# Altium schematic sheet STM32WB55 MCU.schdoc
size 297 x 209 mm; Symbol: Drawing-Symbol_A4; @Project Name: Hưhwwuey; @Page Count: 3; @Update Date: 2026-10-10; @Create Date: 2026-10-10; @Schematic Name: Schematic1; @Page No: 3; @Page Name: P1; Company: EasyEDA.com; Version: V1.0; Page Size: A4; Device: Drawing-Symbol_A4; @Create Time: 11:30:46; @Update Time: 11:30:46; Border: 1; Width: 1170; Height: 825; Region Start: 1; X Region Count: 6; Y Region Count: 4; Blade Width: 10; Title Block Position: 3; @Board Name: Board1
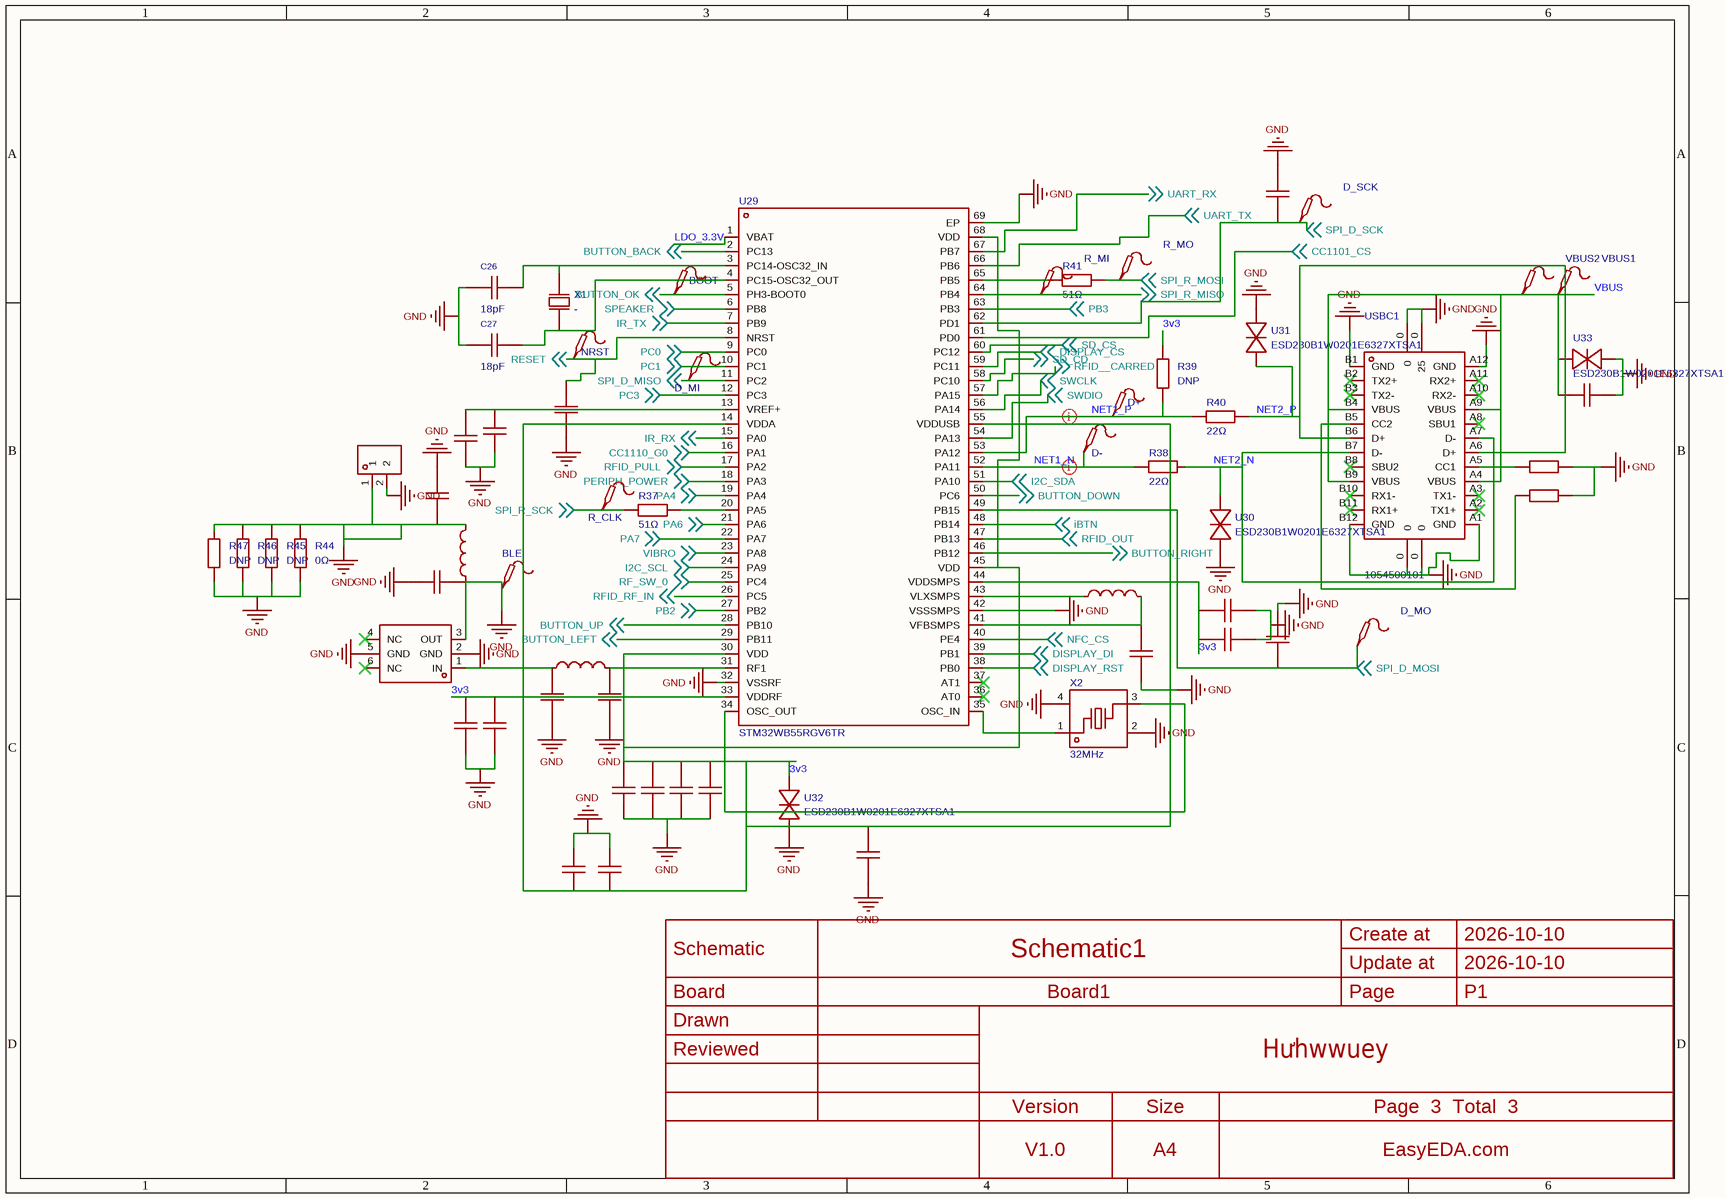
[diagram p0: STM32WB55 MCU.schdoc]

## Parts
C26  18pF  [C0402]
C27  18pF  [C0402]
C28  DNP  [C0402]  (value not drawn)
C29  DNP  [C0402]  (value not drawn)
C30  100nF  [C0402]  (value not drawn)
C31  0.8pf  [C0402]  (value not drawn)
C32  0.3PF  [C0402]  (value not drawn)
C33  100nF  [C0402]  (value not drawn)
C34  100nF  [C0402]  (value not drawn)
C35  100nF  [C0402]  (value not drawn)
C36  4.7uF  [C0402]  (value not drawn)
C37  100nF  [C0402]  (value not drawn)
C38  1nF  [C0402]  (value not drawn)
C39  10nF  [C0402]  (value not drawn)
C40  1nF  [C0402]  (value not drawn)
C41  100nF  [C0402]  (value not drawn)
C42  100nF  [C0402]  (value not drawn)
C43  100pF  [C0402]  (value not drawn)
C44  4.7uF  [C0402]  (value not drawn)
C45  4.7uF  [C0402]  (value not drawn)
C46  100nF  [C0402]  (value not drawn)
C47  100nF  [C0402]  (value not drawn)
C48  1.5pF  [C0402]  (value not drawn)
C49  100nF  [C0402]  (value not drawn)
D-  (no value)  [Test-Point-0.5mm]
FL1  LFL182G45TC1A108  [FILTET-SMD_0603-6P-L1.6-W0.8-P0.50_LFL182G45TC1A108]  (value not drawn)
L4  2.7nh  [L0805]  (value not drawn)
L5  10uH  [L0805]  (value not drawn)
L6  3nH  [L0402]  (value not drawn)
R37  51Ω  [R0402]
R38  22Ω  [R0402]
R39  DNP  [R0402]
R40  22Ω  [R0402]
R41  51Ω  [R0402]
R42  5.1K  [R1206]  (value not drawn)
R43  5.1K  [R1206]  (value not drawn)
R44  0Ω  [R0402]
R45  DNP  [R0402]
R46  DNP  [R0402]
R47  DNP  [R0402]
R_CLK  (no value)  [Test-Point-0.5mm]
TP5  D+  [Test-Point-0.5mm]
TP6  D_MI  [Test-Point-0.5mm]
TP7  R_MI  [Test-Point-0.5mm]
TP8  R_MO  [Test-Point-0.5mm]
TP9  D_MO  [Test-Point-0.5mm]
TP10  D_SCK  [Test-Point-0.5mm]
TP11  BOOT  [Test-Point-0.5mm]
TP12  NRST  [Test-Point-0.5mm]
TP13  VBUS2  [Test-Point-0.5mm]
TP14  VBUS1  [Test-Point-0.5mm]
TP15  BLE  [Test-Point-0.5mm]
U29  STM32WB55RGV6TR  [QFN-68_L8.0-W8.0-P0.40-TL-EP6.4]
U30  ESD230B1W0201E6327XTSA1  [WLL-2-1_L0.6-W0.3-BI]
U31  ESD230B1W0201E6327XTSA1  [WLL-2-1_L0.6-W0.3-BI]
U32  ESD230B1W0201E6327XTSA1  [WLL-2-1_L0.6-W0.3-BI]
U33  ESD230B1W0201E6327XTSA1  [WLL-2-1_L0.6-W0.3-BI]
U34  1001312  [ANT-SMD_L2.0-W1.2-BI]  (value not drawn)
USBC1  1054500101  [USB-C-SMD_TYPE-C-USB-18]
X1  -  [CRYSTAL-SMD_L3.2-W1.5-1]
X2  32MHz  [CRYSTAL-SMD_4P-L3.2-W2.5-BL]

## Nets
GND: C26.1 C27.1 C28.1 C29.1 C30.2 C31.2 C32.2 C33.2 C34.2 C35.2 C36.1 C37.2 C38.2 C39.2 C40.1 C41.2 C42.2 C43.1 C44.1 C45.1 C46.1 C47.1 C48.1 C48.2 C49.1 C49.2 FL1.2(GND) FL1.3(OUT) FL1.5(GND) L6.1 L6.2 R42.2 R43.2 R44.1 R44.2 R45.1 R45.2 R46.1 R46.2 R47.1 R47.2 TP15.1 U29.32(VSSRF) U29.42(VSSSMPS) U29.69(EP) U30.1(C) U31.2(A) U32.1(C) U33.1(C) U34.1 U34.2 USBC1.0 USBC1.A1(GND) USBC1.A12(GND) USBC1.B1(GND) USBC1.B12(GND) X2.2(GND) X2.4(GND)
3v3: C33.1 C34.1 C35.1 C36.2 C37.1 C38.1 C39.1 C42.1 C43.2 C45.2 C46.2 R39.2 U29.14(VDDA) U29.30(VDD) U29.33(VDDRF) U29.44(VDDSMPS) U29.45(VDD) U29.55(VDDUSB) U29.68(VDD) U32.2(A)
BUTTON_BACK: U29.2(PC13) ; off-sheet BUTTON_BACK
BUTTON_DOWN: U29.50(PC6) ; off-sheet BUTTON_DOWN
BUTTON_LEFT: U29.29(PB11) ; off-sheet BUTTON_LEFT
BUTTON_OK: TP11.1 U29.5(PH3-BOOT0) ; off-sheet BUTTON_OK
BUTTON_RIGHT: U29.46(PB12) ; off-sheet BUTTON_RIGHT
BUTTON_UP: U29.28(PB10) ; off-sheet BUTTON_UP
CC1101_CS: U29.61(PD0) ; off-sheet CC1101_CS
CC1110_G0: U29.16(PA1) ; off-sheet CC1110_G0
DISPLAY_CS: U29.59(PC11) ; off-sheet DISPLAY_CS
DISPLAY_DI: U29.39(PB1) ; off-sheet DISPLAY_DI
DISPLAY_RST: U29.38(PB0) ; off-sheet DISPLAY_RST
I2C_SCL: U29.24(PA9) ; off-sheet I2C_SCL
I2C_SDA: U29.51(PA10) ; off-sheet I2C_SDA
iBTN: U29.48(PB14) ; off-sheet iBTN
IR_RX: U29.15(PA0) ; off-sheet IR_RX
IR_TX: U29.7(PB9) ; off-sheet IR_TX
LDO_3.3V: U29.1(VBAT)
NET1_N: D-.1 R38.1 U29.52(PA11)
NET1_P: R39.1 R40.2 TP5.1 U29.53(PA12)
NET2_N: R38.2 U30.2(A) USBC1.A7(D-) USBC1.B7(D-)
NET2_P: R40.1 U31.1(C) USBC1.A6(D+) USBC1.B6(D+)
NFC_CS: U29.40(PE4) ; off-sheet NFC_CS
PA4: U29.19(PA4) ; off-sheet PA4
PA6: U29.21(PA6) ; off-sheet PA6
PA7: U29.22(PA7) ; off-sheet PA7
PB2: U29.27(PB2) ; off-sheet PB2
PB3: U29.63(PB3) ; off-sheet PB3
PC0: U29.9(PC0) ; off-sheet PC0
PC1: U29.10(PC1) ; off-sheet PC1
PC3: U29.12(PC3) ; off-sheet PC3
PERIPH_POWER: U29.18(PA3) ; off-sheet PERIPH_POWER
RESET: C30.1 TP12.1 U29.8(NRST) ; off-sheet RESET
RF_SW_0: U29.25(PC4) ; off-sheet RF_SW_0
RFID__CARRED: U29.57(PA15) ; off-sheet RFID__CARRED
RFID_OUT: U29.47(PB13) ; off-sheet RFID_OUT
RFID_PULL: U29.17(PA2) ; off-sheet RFID_PULL
RFID_RF_IN: U29.26(PC5) ; off-sheet RFID_RF_IN
SD_CD: U29.58(PC10) ; off-sheet SD_CD
SD_CS: U29.60(PC12) ; off-sheet SD_CS
SPEAKER: U29.6(PB8) ; off-sheet SPEAKER
SPI_D_MISO: TP6.1 U29.11(PC2) ; off-sheet SPI_D_MISO
SPI_D_MOSI: C28.2 TP9.1 U29.49(PB15) ; off-sheet SPI_D_MOSI
SPI_D_SCK: C29.2 TP10.1 U29.62(PD1) ; off-sheet SPI_D_SCK
SPI_R_MISO: TP7.1 U29.64(PB4) ; off-sheet SPI_R_MISO
SPI_R_MOSI: R41.2 TP8.1 ; off-sheet SPI_R_MOSI
SPI_R_SCK: R37.1 R_CLK.1 ; off-sheet SPI_R_SCK
SWCLK: U29.56(PA14) ; off-sheet SWCLK
SWDIO: U29.54(PA13) ; off-sheet SWDIO
UART_RX: U29.67(PB7) ; off-sheet UART_RX
UART_TX: U29.66(PB6) ; off-sheet UART_TX
VBUS: C47.2 TP13.1 TP14.1 U33.2(A) USBC1.A4(VBUS) USBC1.A9(VBUS) USBC1.B4(VBUS) USBC1.B9(VBUS)
VIBRO: U29.23(PA8) ; off-sheet VIBRO
NetC26_2: C26.2 U29.3(PC14-OSC32_IN) X1.1(OSC1)
NetC27_2: C27.2 U29.4(PC15-OSC32_OUT) X1.2(OSC2)
NetC31_1: C31.1 L4.2 U29.31(RF1)
NetC32_1: C32.1 FL1.1(IN) L4.1
NetC40_2: C40.2 C41.1 U29.13(VREF+)
NetC44_2: C44.2 L5.2 U29.41(VFBSMPS)
NetL5_1: L5.1 U29.43(VLXSMPS)
NetR37_2: R37.2 U29.20(PA5)
NetR41_1: R41.1 U29.65(PB5)
NetR42_1: R42.1 USBC1.A5(CC1)
NetR43_1: R43.1 USBC1.B5(CC2)
NetU29_34: U29.34(OSC_OUT) X2.3
NetU29_35: U29.35(OSC_IN) X2.1

Not connected (* = marked no-connect by the designer): FL1 4(NC)* 6(NC)*; U29 36(AT0)* 37(AT1)*; USBC1 A2(TX1+)* A3(TX1-)* A8(SBU1)* A10(RX2-)* A11(RX2+)* B2(TX2+)* B3(TX2-)* B8(SBU2)* B10(RX1-)* B11(RX1+)*

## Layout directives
differential pair; Symbol: Differential-Pairs-Flag; Device: Differential-Pairs-Flag: NET1_N, NET1_P

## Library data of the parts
C26 C27 = CC0402FRNPO9BN180: Capacitance:18pF Tolerance:±1% Tolerance:±1% Voltage Rating:50V Temperature Coefficient:NP0; Manufacturer: YAGEO(国巨); AddInBom: yes; ModelId: b7d13df3e9464d7a99d0651d1a5b4d570819f05c4eef4c71ace90d822a990e87; ModelName: C0402_L1.0-W0.5-H0.5; ModelTransform: 39.37,19.685,0,0,0,0,0,0,0; Tolerance: ±1%; Voltage Rating: 50V; Temperature Coefficient: NP0
C28 C29 C31 C32 C49 = CAP_0402: Symbol: CAP_OLD; Add into BOM: no; ConvertToPcb: yes; ModelId: b7d13df3e9464d7a99d0651d1a5b4d570819f05c4eef4c71ace90d822a990e87; ModelName: C0402_L1.0-W0.5-H0.5; ModelTransform: 39.37,19.685,0,0,0,0,0,0,0
C30 C33-C35 C37 C41 C42 C46 C47 = CAP_0402: Symbol: CAP_OLD; ConvertToPcb: yes; ModelId: b7d13df3e9464d7a99d0651d1a5b4d570819f05c4eef4c71ace90d822a990e87; ModelName: C0402_L1.0-W0.5-H0.5; ModelTransform: 39.37,19.685,0,0,0,0,0,0,0
C36 C44 C45 = CL05A475MP5NRNC: Capacitance:4.7uF Tolerance:±20% Tolerance:±20% Voltage Rating:10V Temperature Coefficient:X5R; Manufacturer: SAMSUNG(三星); AddInBom: yes; ModelId: b7d13df3e9464d7a99d0651d1a5b4d570819f05c4eef4c71ace90d822a990e87; ModelName: C0402_L1.0-W0.5-H0.5; ModelTransform: 39.37,19.685,0,0,0,0,0,0,0; Tolerance: ±20%; Voltage Rating: 10V; Temperature Coefficient: X5R
C38 C40 = CC0402KRX7R9BB102: Capacitance: Tolerance:±10% Tolerance:±10% Voltage Rated: Temperature Coefficient:; Manufacturer: YAGEO(国巨); AddInBom: yes; ModelId: b7d13df3e9464d7a99d0651d1a5b4d570819f05c4eef4c71ace90d822a990e87; ModelName: C0402_L1.0-W0.5-H0.5; ModelTransform: 39.37,19.685,0,0,0,0,0,0,0; Tolerance: ±10%
C39 = CC0402KRX7R9BB103: Capacitance:10nF Tolerance:±10% Tolerance:±10% Voltage Rating:50V Temperature Coefficient:X7R; Manufacturer: YAGEO(国巨); AddInBom: yes; ModelId: b7d13df3e9464d7a99d0651d1a5b4d570819f05c4eef4c71ace90d822a990e87; ModelName: C0402_L1.0-W0.5-H0.5; ModelTransform: 39.37,19.685,0,0,0,0,0,0,0; Tolerance: ±10%; Voltage Rating: 50V; Temperature Coefficient: X7R
C43 = TCC0402COG101K500AT: Capacitance:100pF Tolerance:±10% Tolerance:±10% Voltage Rating:50V Temperature Coefficient:C0G; Manufacturer: CCTC(三环); AddInBom: yes; ModelId: b7d13df3e9464d7a99d0651d1a5b4d570819f05c4eef4c71ace90d822a990e87; ModelName: C0402_L1.0-W0.5-H0.5; ModelTransform: 39.37,19.685,0,0,0,0,0,0,0; Tolerance: ±10%; Voltage Rating: 50V; Temperature Coefficient: C0G
C48 = CBR04C159B1GAC: Capacitance:1.5pF Voltage Rating:100V Temperature Coefficient:C0G; Manufacturer: KEMET(基美); AddInBom: yes; ModelId: b7d13df3e9464d7a99d0651d1a5b4d570819f05c4eef4c71ace90d822a990e87; ModelName: C0402_L1.0-W0.5-H0.5; ModelTransform: 39.37,19.685,0,0,0,0,0,0,0; Voltage Rating: 100V; Temperature Coefficient: C0G
D- R_CLK TP5-TP15 = Test-Point: Test Point 测试点; AddInBom: yes
FL1 = LFL182G45TC1A108: Filter Type:Low Pass Frequency - Center:2.45GHz Cut-Off Frequency:- Absolute Bandwidth:- Absolute Bandwidth:- Relative Bandwidth:±50MHz Relative Bandwidth:±50MHz Attenuation:25dB；27dB Impedance:- Ripple:- Insertion Loss:0.37dB Operating Temperature:- Oper; Manufacturer: muRata(村田); AddInBom: yes; ModelId: 51cd48ced02d43649b0133f35344f5780819f05c4eef4c71ace90d822a990e87; ModelTransform: 62.992,32.283,0,0,0,0,0,0,0; Relative Bandwidth: ±50MHz; Insertion Loss: 0.37dB
L4 = L_0805: Symbol: 电感; Add into BOM: no; ConvertToPcb: yes; ModelId: b83c7c5430874b8eb2319a65d94334290819f05c4eef4c71ace90d822a990e87; ModelName: R0805_L2.0-W1.3-H0.6; ModelTransform: 78.74,51.181,0,0,0,0,0,0.001,0
L5 = CMI201209X100KT: Inductance: Tolerance:±10% Tolerance:±10% Rated Current: Saturation Current (Isat):- DC Resistance (DCR): Q @ Freq:30@2MHz Frequency - Self Resonant: Ratings:; Manufacturer: FH(风华); AddInBom: yes; ModelId: b83c7c5430874b8eb2319a65d94334290819f05c4eef4c71ace90d822a990e87; ModelName: R0805_L2.0-W1.3-H0.6; ModelTransform: 78.74,51.181,0,0,0,0,0,0.001,0; Tolerance: ±10%
L6 = VHF100505HQ3N0BT: Inductance:3nH Current Rating:800mA Current - Saturation (Isat):- DC Resistance(DCR):120mΩ Q @ Frequency:8@100MHz Frequency - Self Resonant:6GHz Type:Multilayer inductor；High-frequency inductor; Manufacturer: FH(风华); AddInBom: yes; ModelId: aef00b1603224fd68a96e37121ccc9160819f05c4eef4c71ace90d822a990e87; ModelName: L0402_L1.0-W0.5-H0.5_BEAD; ModelTransform: 39.37,19.685,0,0,0,0,0,0.0005,0; Current Rating: 800mA; DC Resistance(DCR): 120mΩ; Frequency - Self Resonant: 6GHz
R37 R41 = CR0402FF51R0G: Type:Thick Film Resistor Resistance:51Ω Tolerance:±1% Tolerance:±1% Power(Watts):62.5mW Voltage-Supply(Max):50V Temperature Coefficient:±200ppm/℃ Temperature Coefficient:±200ppm/℃ Operating Temperature:-55℃~+125℃ Operating Temperature:-55℃~+125℃; Manufacturer: LIZ(丽智电子); 3D Model: efdecb7dae4442949d28eecaf748420f0819f05c4eef4c71ace90d822a990e87; 3D Model Transform: 39.37,19.685,0,0,0,0,0,0,0; Tolerance: ±1%; Power(Watts): 62.5mW; Voltage-Supply(Max): 50V; AddInBom: yes; ModelName: R0402_L1.0-W0.5-H0.4
R38 = CR0402FF22R0G: Type:Thick Film Resistor Resistance:22Ω Tolerance:±1% Tolerance:±1% Power(Watts):62.5mW Voltage-Supply(Max):50V Temperature Coefficient:±200ppm/℃ Temperature Coefficient:±200ppm/℃ Operating Temperature:-55℃~+125℃ Operating Temperature:-55℃~+125℃; Manufacturer: LIZ(丽智电子); AddInBom: yes; ModelId: efdecb7dae4442949d28eecaf748420f0819f05c4eef4c71ace90d822a990e87; ModelName: R0402_L1.0-W0.5-H0.4; ModelTransform: 39.37,19.685,0,0,0,0,0,0,0; Tolerance: ±1%; Power(Watts): 62.5mW; Voltage-Supply(Max): 50V
R39 = Res_0402: Symbol: Res; 3D Model: efdecb7dae4442949d28eecaf748420f0819f05c4eef4c71ace90d822a990e87; 3D Model Transform: 39.37,19.685,0,0,0,0,0,0,0; Add into BOM: no; ConvertToPcb: yes; ModelName: R0402_L1.0-W0.5-H0.4
R40 = CR0402FF22R0G: Type:Thick Film Resistor Resistance:22Ω Tolerance:±1% Tolerance:±1% Power(Watts):62.5mW Voltage-Supply(Max):50V Temperature Coefficient:±200ppm/℃ Temperature Coefficient:±200ppm/℃ Operating Temperature:-55℃~+125℃ Operating Temperature:-55℃~+125℃; Manufacturer: LIZ(丽智电子); 3D Model: efdecb7dae4442949d28eecaf748420f0819f05c4eef4c71ace90d822a990e87; 3D Model Transform: 39.37,19.685,0,0,0,0,0,0,0; Tolerance: ±1%; Power(Watts): 62.5mW; Voltage-Supply(Max): 50V; AddInBom: yes; ModelName: R0402_L1.0-W0.5-H0.4
R42 R43 = Res_1206: Symbol: Res; Add into BOM: no; ConvertToPcb: yes; ModelId: 04f48aacb8114155959811d2338bbb060819f05c4eef4c71ace90d822a990e87; ModelName: R1206_L3.2-W1.6-H0.6; ModelTransform: 125.984,62.992,0,0,0,0,0,0,0
R44 = MR04X000PTL: Type:Thick Film Resistors Resistance: Power(Watts): Overload Voltage (Max): Temperature Coefficient:-200ppm/℃~+400ppm/℃ Temperature Coefficient:-200ppm/℃~+400ppm/℃ Operating Temperature Range:-55℃~+155℃ Operating Temperature Range:-55℃~+155℃; Manufacturer: Walsin(华新科); Symbol: MR04X000PTL_C396825; AddInBom: yes; ModelId: efdecb7dae4442949d28eecaf748420f0819f05c4eef4c71ace90d822a990e87; ModelName: R0402_L1.0-W0.5-H0.4; ModelTransform: 39.37,19.685,0,0,0,0,0,0,0
R45-R47 = MR04X000PTL: Type:Thick Film Resistors Resistance: Power(Watts): Overload Voltage (Max): Temperature Coefficient:-200ppm/℃~+400ppm/℃ Temperature Coefficient:-200ppm/℃~+400ppm/℃ Operating Temperature Range:-55℃~+155℃ Operating Temperature Range:-55℃~+155℃; Manufacturer: Walsin(华新科); Symbol: MR04X000PTL_C396825; Add into BOM: no; ConvertToPcb: yes; ModelId: efdecb7dae4442949d28eecaf748420f0819f05c4eef4c71ace90d822a990e87; ModelName: R0402_L1.0-W0.5-H0.4; ModelTransform: 39.37,19.685,0,0,0,0,0,0,0
U29 = STM32WB55RGV6TR: CPU Core:ARM Cortex-M4 CPU Maximum Speed:64MHz；32MHz Core Size:32 Bit Program Storage Size:1MB Program Memory Type:FLASH RAM Size:256KB EEPROM:- Number of I/O:49 ADC (Bit):12bit DAC (Bit):- Oscillator Type:Built-in+External Voltage - Supply:1.71V~3.6V Vol; Manufacturer: ST(意法半导体); AddInBom: yes; ModelId: d6365783f38a4a3f8278ff48575fb0440819f05c4eef4c71ace90d822a990e87; ModelTransform: 315.03874,315.03874,0,0,0,0,0,0,0; Core Size: 32 Bit; Program Storage Size: 1MB; Program Memory Type: FLASH; RAM Size: 256KB; Number of I/O: 49; ADC (Bit): 12bit
U30-U33 = ESD230B1W0201E6327XTSA1: Reverse Stand-Off Voltage (Vrwm):5.5V Clamping Voltage:15V Peak Pulse Current (Ipp):3A@8/20us Peak Pulse Power Dissipation (Ppp):56W Voltage - Breakdown:6.05V Reverse Leakage Current (Ir):1nA Operating Temperature:-55℃~+125℃ Operating Temperature:-55℃~+12; Manufacturer: Infineon(英飞凌); 3D Model: e9ba6bad375e4bb7980be781c89bfdc60819f05c4eef4c71ace90d822a990e87; 3D Model Transform: 22.8346,11.0236,0,0,0,0,0,0,0; Reverse Stand-Off Voltage (Vrwm): 5.5V; Clamping Voltage: 15V; Peak Pulse Power Dissipation (Ppp): 56W; Voltage - Breakdown: 6.05V; Reverse Leakage Current (Ir): 1nA; level of protection: IEC 61000-4-4；IEC 61000-4-5；IEC 61000-4-2; Junction Capacitance: 7pF; AddInBom: yes
U34 = 1001312: Antenna Type:Ceramic Antenna Frequency(Center/Band):2.4425GHz；7.25GHz Bandwidth:2.5GHz；85MHz Peak Gain:1.88dBi；4.8dBi Peak Gain:1.88dBi；4.8dBi Impedance:50Ω Power:500mW VSWR:1.8 Operating Temperature:- Operating Temperature:-; Manufacturer: Kyocera AVX; AddInBom: yes; ModelId: 2c7f90f7db734f4186af3f2973be3da30819f05c4eef4c71ace90d822a990e87; ModelTransform: 79.527,48.0314,0,0,0,0,0,0,0; Impedance: 50Ω; Power: 500mW; VSWR: 1.8
USBC1 = 1054500101: Connector Type:Type-C Protocol Standard:USB 3.2 Gender:Female Number of Contacts:24P Number of Ports:1 Current Rating-Power:- Voltage Rating:30V Connect-Disconnect Life:10000 times Detection color:Black Operating Temperature:-30℃~+85℃ Operating Temperatur; Manufacturer: MOLEX; Symbol: 105450-0101; AddInBom: yes; ModelId: 0a8b179b074640028ea4e7f9717cab390819f05c4eef4c71ace90d822a990e87; ModelTransform: 351.9678,311.023,0,180,0,0,0,-36.418,-39.37; Connector Type: Type-C; Protocol Standard: USB 3.2; Gender: Female; Number of Contacts: 24P; Number of Ports: 1; Voltage Rating: 30V; Detection color: Black
X1 = SF32K32768D31T-12.5B: Type:Crystal Oscillator Frequency:- Load Capacitance:- Operating Temperature:- Operating Temperature:-; Manufacturer: TKD(泰晶); AddInBom: yes; ModelId: 628c7126ebe04166b34fd3fa8c4da1390819f05c4eef4c71ace90d822a990e87; ModelTransform: 125.984,59.055,0,0,0,0,0,0,0
X2 = Y322532MCBCX: Type:Crystal Oscillator Frequency:32MHz Normal temperature Frequency Tolerance:±10ppm Normal temperature Frequency Tolerance:±10ppm Load Capacitance:8pF Frequency Stability:±20ppm Frequency Stability:±20ppm Operating Temperature:-40℃~+85℃ Operating Temper; Manufacturer: JLYE(晶力源); AddInBom: yes; ModelId: a2b47bc5d32f4dfd996128e047b549a00819f05c4eef4c71ace90d822a990e87; ModelTransform: 125.984,98.425,0,0,0,0,0,0,0; Normal temperature Frequency Tolerance: ±10ppm; Load Capacitance: 8pF; Frequency Stability: ±20ppm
